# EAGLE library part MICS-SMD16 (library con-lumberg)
CONNECTOR
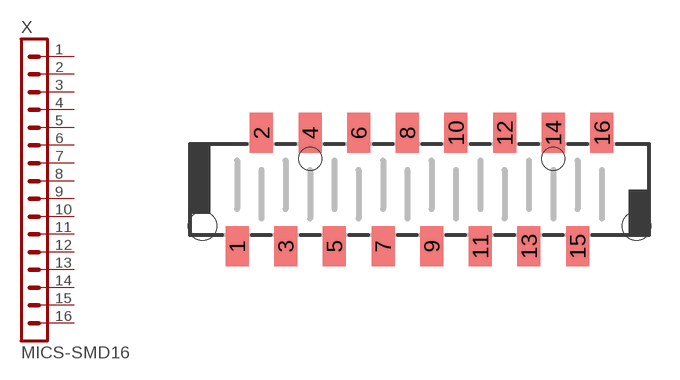
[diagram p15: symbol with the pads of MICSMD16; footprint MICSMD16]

Designator prefix X

## MICS-SMD16 (OC_FARNELL: unknown; OC_NEWARK: unknown)  [MICSMD16]
1  1  pas
2  2  pas
3  3  pas
4  4  pas
5  5  pas
6  6  pas
7  7  pas
8  8  pas
9  9  pas
10  10  pas
11  11  pas
12  12  pas
13  13  pas
14  14  pas
15  15  pas
16  16  pas

## Footprint MICSMD16 (pad centres in mm)
CONNECTOR
smd 1.2 x 2.1: 1 -9.525,-2.959; 2 -8.255,2.959; 3 -6.985,-2.959; 4 -5.715,2.959; 5 -4.445,-2.959; 6 -3.175,2.959; 7 -1.905,-2.959; 8 -0.635,2.959; 9 0.635,-2.959; 10 1.905,2.959; 11 3.175,-2.959; 12 4.445,2.959; 13 5.715,-2.959; 14 6.985,2.959; 15 8.255,-2.959; 16 9.525,2.959
hole 1.5 at 11.325,-1.912
hole 1.5 at -11.325,-1.912
hole 1.2 at -5.715,1.6
hole 1.2 at 6.985,1.6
